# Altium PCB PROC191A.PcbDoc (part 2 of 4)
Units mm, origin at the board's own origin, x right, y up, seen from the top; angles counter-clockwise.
Board outline 150 x 100 mm, 6 copper layers (L1, L2, L3, L4, L5, L6), stack 1.608 mm thick; 309 components, 191 nets, 851 pads, 778 vias.
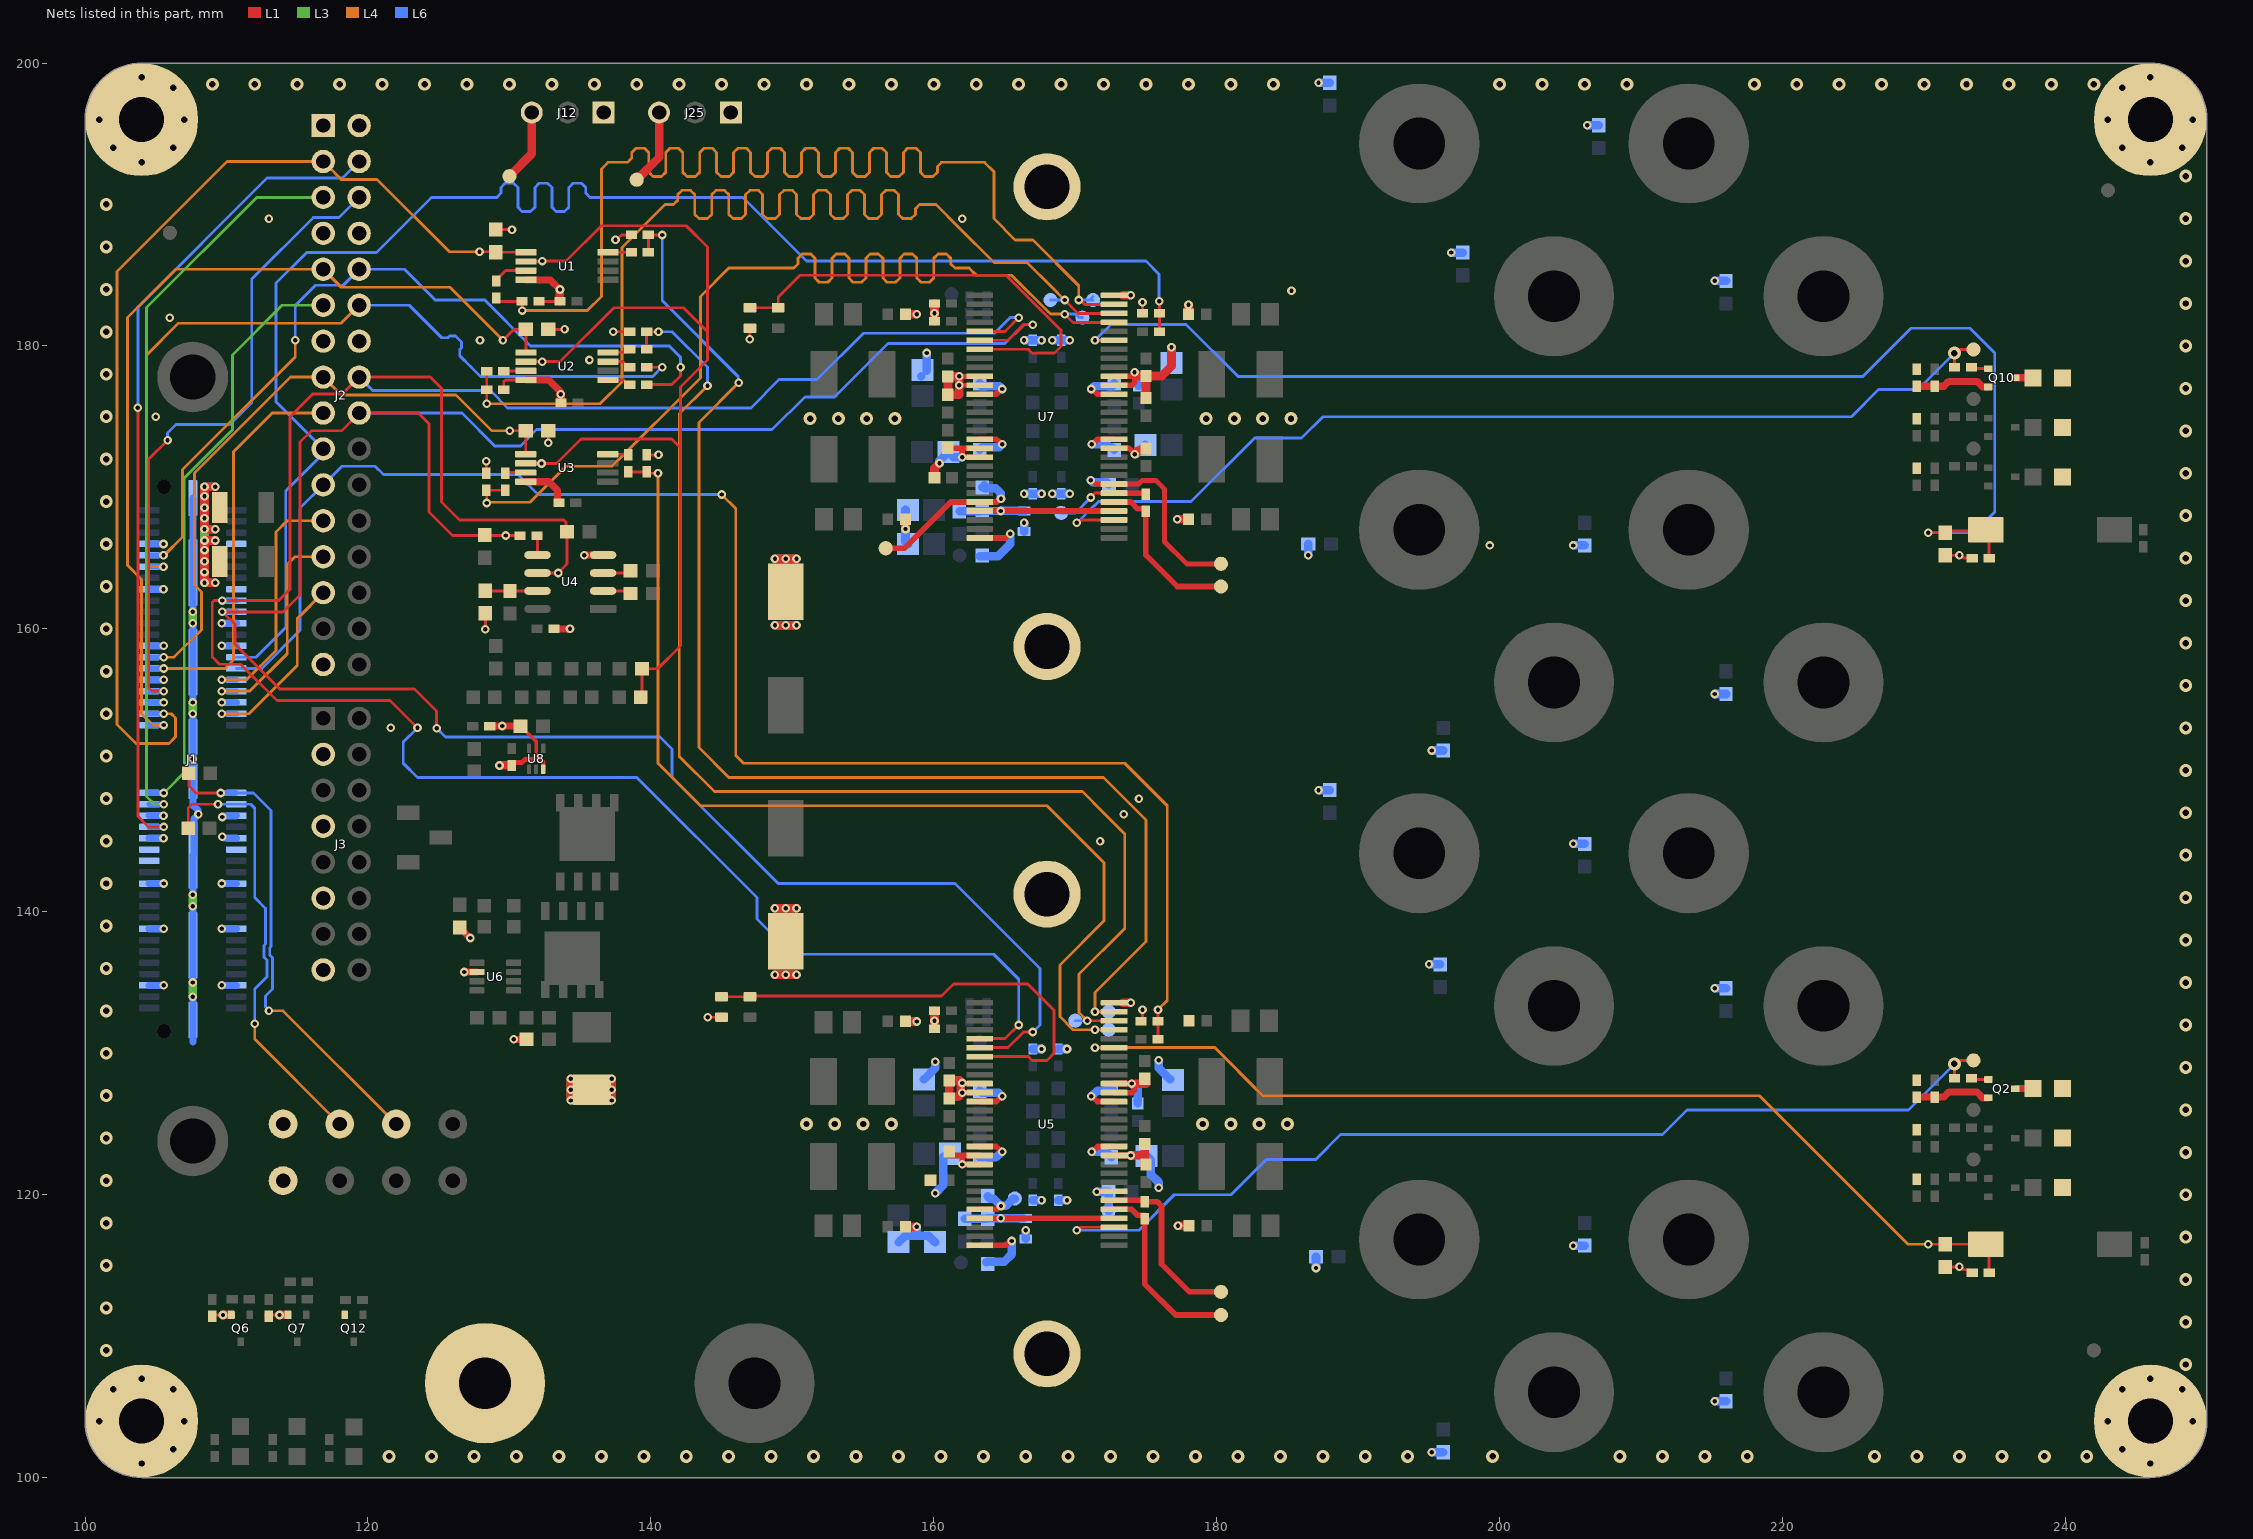
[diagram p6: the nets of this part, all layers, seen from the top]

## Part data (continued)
D5 D6 D11: library part CMP-0002888-2, "LED, Green, SMD", Color=Green, Manufacturer=Lite-On, Value1=W, Value2=2V
FID1 FID2 FID3 FID4 FID5 FID6: library part CMP-0077181-1, "Fiducial mark.  There is nothing to buy or mount.", Manufacturer=N/A
H1 H2: library part CMP-0123147-2, "20.0 x 41.4 x 32.8 mm  BGA Heat Sink - High Performance Device Specific - TI", Digikey Part Number=684-ATS-TI1OP-1918-C1-R0-ND, Manufacturer="Advanced Thermal Solutions", Operating Temperature Range=to, Thermal Resistance Forced Air Flow=4.6°C/W
J1: library part CMP-0091968-1, "80 Position Connector Header, Outer Shroud Contacts Surface Mount Gold", Digikey Part Number=SAM8132-ND, Manufacturer=Samtec, Mouser Part Number=200-QTE04001LDA, Operating Temperature Range="-55°C to +125°C", Voltage_V=225V
J2: library part CMP-0075429-1, "Header, 100mil, 16x2, Gold, TH", Color=Black, Current_A=6.3A, Manufacturer=Samtec, Supplier Part Number 1=SAM1028-16-ND, Voltage_V=550V
J3: library part CMP-0075418-1, "Header, 100mil, 8x2, Gold, TH", Color=Black, Current_A=6.3A, Manufacturer=Samtec, Supplier Part Number 1=SAM1028-08-ND, Voltage_V=550V
J4 J6 J8 J10 J13 J17 J19 J21 J23: library part CMP-0055127-1, "Binding Post, RED, TH", Manufacturer=Keystone, Supplier Part Number 1=36-7006-ND
J5 J7 J9 J11 J15 J18 J20 J22 J24: library part CMP-0055128-1, "Binding Post, BLACK, TH", Manufacturer=Keystone, Supplier Part Number 1=36-7007-ND
J12 J25: library part CMP-0055322-1, "Header, 2.54 mm, 3x1, Tin, TH", Color=White, Manufacturer=Molex, Supplier Part Number 1=WM4201-ND
L1 L2 L3 L4 L6 L7 L8 L9: library part CMP-0059924-1, "Inductor, 3.3 uH, 4.5 A, 0.038 ohm, AEC-Q200 Grade 0, SMD", Manufacturer=Cyntec, Value1="0.038 ohm", Value2=4.5A, ValueDisplayed=3.3uH
Logo1: library part CMP-0074844-2, Manufacturer="Texas Instruments"
Logo2: library part CMP-0074838-1, "Texas Instrument Corporate Signature"
Logo3: library part CMP-0074847-1, "FCC_disclaimer"
Logo4: library part CMP-0074769-4, Manufacturer="Texas Instruments"
Q1 Q2 Q3 Q9 Q10 Q11: library part CMP-0000010-3, "MOSFET, P-CH, -20 V, -0.39 A, SOT-323", Alternate Manufacturer=None, Manufacturer="Infineon Technologies", Value1=1
Q4 Q5: library part CMP-0000665-1, "MOSFET, N-CH, 30 V, 15 A, PowerPAK SO-8", Alternate Manufacturer=None, Manufacturer=Vishay-Siliconix, Supplier Part Number 1=SI7892BDP-T1-E3CT-ND, Value1=0.005, Value2="27 nC"
Q6 Q7 Q12: library part CMP-0000948-2, "MOSFET, N-CH, 100 V, 0.17 A, SOT-323", Alternate Manufacturer=None, Manufacturer="Diodes Inc.", Supplier Part Number 1=BSS123W-FDICT-ND, Value1=1
R1 R3 R9 R10 R11 R12 R14 R15 R19 R33 R78: library part CMP-0026997-2, "RES, 22, 5%, 0.1 W, AEC-Q200 Grade 0, 0402", Manufacturer=Panasonic, Power_W=100mW, Supplier Part Number 1=P22JCT-ND, TempCo="200 ppm/C", Tolerance_%=5%, Value2=0.1W, Value_Code=22R0, ValueDisplayed=22
R2 R17 R18 R20 R52 R54 R94: library part CMP-0022746-5, "RES, 10.0 k, 1%, 0.1 W, 0603", Manufacturer=Yageo, Power_W=100mW, Supplier Part Number 1=311-10.0KHRCT-ND, TempCo="100 ppm/C", Tolerance_%=1%, Value2=0.1W, Value_Code=10k0, ValueDisplayed=10.0k
R4 R41 R49 R53 R55 R74 R83 R86 R95: library part CMP-0089143-1, "0 Ohms Jumper 0.1W, 1/10W Chip Resistor 0603 (1608 Metric) Automotive AEC-Q200 Thick Film", Digikey Part Number=P0.0GCT-ND, Manufacturer=Panasonic, Mouser Part Number=667-ERJ-3GEY0R00V, Operating Temperature Range="-55°C to +155°C", Power_W=100mW, TempCo=-100/+600ppm/°C, Tolerance_%=5%
R5 R56 R57: library part CMP-0078194-1, "RES, 360, 5%, 0.1 W, AEC-Q200 Grade 0, 0402", Manufacturer=Panasonic, Power_W=100mW, Supplier Part Number 1=P360JCT-ND, TempCo="200 ppm/C", Tolerance_%=5%, Value2=0.1W, Value_Code=360R, ValueDisplayed=360
R6 R13 R16 R21 R38 R50: library part CMP-0022735-5, "RES, 100 k, 1%, 0.1 W, 0603", Manufacturer=Yageo, Power_W=100mW, Supplier Part Number 1=311-100KHRCT-ND, TempCo="100 ppm/C", Tolerance_%=1%, Value2=0.1W, Value_Code=100k
R7 R8: library part CMP-0023155-5, "RES, 4.99 k, 1%, 0.1 W, 0603", Manufacturer=Yageo, Power_W=100mW, Supplier Part Number 1=311-4.99KHRCT-ND, TempCo="100 ppm/C", Tolerance_%=1%, Value2=0.1W, Value_Code=4k99, ValueDisplayed=4.99k
R22 R23 R24 R25 R67 R68 R69 R70: library part CMP-0026753-1, "RES, 100 k, 1%, 0.063 W, AEC-Q200 Grade 0, 0402", Manufacturer="Stackpole Electronics Inc", Power_W=63mW, Supplier Part Number 1=RMCF0402FT100KCT-ND, TempCo="100 ppm/C", Tolerance_%=1%, Value2=0.063W, Value_Code=100k
R26 R31 R34 R36 R71 R76 R79 R81: library part CMP-0025805-4, "RES, 3.3, 5%, 0.1 W, AEC-Q200 Grade 0, 0603", Manufacturer=Vishay-Dale, Power_W=100mW, Supplier Part Number 1=541-3.3GCT-ND, TempCo="200 ppm/C", Tolerance_%=5%, Value2=0.1W, Value_Code=3R30, ValueDisplayed=3.3
R27 R43 R44 R48 R61 R62 R88 R89 R93: library part CMP-0078212-1, "RES, 510, 5%, 0.1 W, AEC-Q200 Grade 0, 0402", Manufacturer=Panasonic, Power_W=100mW, Supplier Part Number 1=P510JCT-ND, TempCo="200 ppm/C", Tolerance_%=5%, Value2=0.1W, Value_Code=510R, ValueDisplayed=510
R28 R29 R30 R73 R75: library part CMP-0089144-1, "1 kOhms ±5% 0.1W, 1/10W Chip Resistor 0603 (1608 Metric) Automotive AEC-Q200 Thick Film", Digikey Part Number=P1.0KGCT-ND, Manufacturer=Panasonic, Mouser Part Number=667-ERJ-3GEYJ102V, Operating Temperature Range="-55°C to +155°C", Power_W=100mW, TempCo=200ppm/°C, Tolerance_%=5%, Voltage=75V
R32 R35: library part CMP-0022752-4, "RES, 110 k, 1%, 0.1 W, 0603", Manufacturer=Yageo, Power_W=100mW, Supplier Part Number 1=311-110KHRCT-ND, TempCo="100 ppm/C", Tolerance_%=1%, Value2=0.1W, Value_Code=110k
R37 R39 R40 R42 R45 R46 R58 R60 R63 R66 R72 R77: library part CMP-0026680-1, "RES, 220, 1%, 0.1 W, AEC-Q200 Grade 0, 0402", Manufacturer=Panasonic, Power_W=100mW, Supplier Part Number 1=P220LCT-ND, TempCo="100 ppm/C", Tolerance_%=1%, Value2=0.1W, Value_Code=220R, ValueDisplayed=220
R47 R90: library part CMP-0026754-1, "RES, 10.0 k, 1%, 0.063 W, AEC-Q200 Grade 0, 0402", Manufacturer="Stackpole Electronics Inc", Power_W=63mW, Supplier Part Number 1=RMCF0402FT10K0CT-ND, TempCo="100 ppm/C", Tolerance_%=1%, Value2=0.063W, Value_Code=10k0, ValueDisplayed=10.0k
R51: library part CMP-0023253-5, "RES, 6.80 k, 1%, 0.1 W, 0603", Manufacturer=Yageo, Power_W=100mW, Supplier Part Number 1=311-6.80KHRCT-ND, TempCo="100 ppm/C", Tolerance_%=1%, Value2=0.1W, Value_Code=6k80, ValueDisplayed=6.80k
R59 R64 R65: library part CMP-0026658-1, "RES, 10.0 k, 1%, 0.1 W, 0402", Manufacturer=Panasonic, Power_W=100mW, Supplier Part Number 1=P10.0KLCT-ND, TempCo="100 ppm/C", Tolerance_%=1%, Value2=0.1W, Value_Code=10k0, ValueDisplayed=10.0k
R96: library part CMP-0023048-4, "RES, 357 k, 1%, 0.1 W, 0603", Manufacturer=Yageo, Power_W=100mW, Supplier Part Number 1=311-357KHRCT-ND, TempCo="100 ppm/C", Tolerance_%=1%, Value2=0.1W, Value_Code=357k
S1: library part CMP-0002139-2, "Switch, Slide, SPDT  100mA, SMT", CurrentRating_mA=100A, Manufacturer="Copal Electronics", Supplier Part Number 1=CAS120JCT-ND
SW2 SW4: library part CMP-0120665-1, "DIP Switch, 1 POS, SPST, Raised, 6VDC, 100mA, CFS Series", Coil Resistance_ohm=50mΩ, Contact Current Rating=100mA, Digikey Part Number=563-CFS-0103CT-ND, Manufacturer="Nidec Components Corporation", Mouser Part Number=229-CFS-0103TB, Operating Temperature Range="-40°C to +85°C"
TP1 TP2 TP3 TP7 TP8 TP9 TP10 TP11 TP12 TP13 TP14 TP15 TP16 TP17 TP18 TP19 TP23 TP24 TP25 TP26 TP27 TP28 TP29 TP30 TP31 TP32: library part CMP-0003825-1, "1mm Test Point, SMT", Manufacturer=Any, PartNumber=TP_SM_1MM
TP4 TP6 TP33: library part CMP-0055137-2, "Test Point, Miniature, Red, TH", Color=Red, Manufacturer="Keystone Electronics", Supplier Part Number 1=36-5000-ND
TP5 TP20 TP22: library part CMP-0055140-2, "Test Point, Miniature, Orange, TH", Color=Orange, Manufacturer="Keystone Electronics", Supplier Part Number 1=36-5003-ND
TP34 TP35: library part CMP-0055138-2, "Test Point, Miniature, Black, TH", Color=Black, Manufacturer="Keystone Electronics", Supplier Part Number 1=36-5001-ND
U1 U3: library part CMP-0091149-1, "Clock Clock Buffer IC 1:4 250MHz 8-TSSOP (0.173\", 4.40mm Width)", Digikey Part Number=296-LMK1C1102PWRCT-ND, Manufacturer="Texas Instruments", Max Supply Voltage=3.465V, Min Supply Voltage=1.71V, Mouser Part Number=595-LMK1C1102PWR, Nominal Supply Current=25-33000uA, Operating Temperature Range="-40°C to +125°C"
U2: library part CMP-0096980-1, "1.8-V, 2.5-V, and 3.3-V LVCMOS Clock Buffer Family", Digikey Part Number=296-LMK1C1104PWRCT-ND, Manufacturer="Texas Instruments", Max Supply Voltage=3.465V, Min Supply Voltage=1.71V, Mouser Part Number=595-LMK1C1104PWR, Nominal Supply Current=25-33000uA, Operating Temperature Range="-40°C to +125°C"
U4: library part CMP-0097697-1, "EEPROM Memory IC 4Kbit I²C 400 kHz 900 ns 8-SOIC", Digikey Part Number=CAT24C04WI-GT3OSCT-ND, Frequency_Fixed=400kHz, Manufacturer="ON Semi", Max Supply Voltage=5.5V, Min Supply Voltage=1.7V, Mouser Part Number=698-CAT24C04WI-GT3, Nominal Supply Current=1-2mA, Operating Temperature Range="-40°C to +85°C"
U5 U7: library part CMP-0096441-1, "26.4 V, 7.5 A Digital Input 4-Channel Automotive Class-D Audio Amplifier with Current Sense and Real-time Load Diagnostics", Manufacturer="Texas Instruments", Max Supply Voltage=26.4V, Min Supply Voltage=4.5V, Operating Temperature Range="-40°C to +125°C", Part Number=TAS6554QDKQRQ1, Power At Speaker R="50W @ 2Ω"
U6: library part CMP-0095578-1, "Low IQ High Side Switch Controller With Reverse Polarity and Overvoltage Protection", Manufacturer="Texas Instruments", Max Supply Voltage=60V, Min Supply Voltage=4V, Nominal Supply Current=45uA, Operating Temperature Range="-40°C to +150°C", Part Number=LM74502QDDFRQ1
U8: library part CMP-0051698-3, "Low-Power Single Schmitt-Trigger Buffer, DRL0005A", Alternate Manufacturer="Texas Instruments", F @ Nom Voltage(Max)(Mhz)=100, Generic Part Number=SN74AUP1G17, ICC @ Nom Voltage(Max)(mA)=0.0009, Operating Temperature Range(C)="-40 to 85", Rating=Catalog, tpd @ Nom Voltage(Max)(ns)=35.1,18.1,12.9,11,7.9,6.7, Voltage(Nom)(V)=0.8,1.2,1.5,1.8,2.5,3.3
ZZ2: library part CMP-0077236-1
ZZ3: library part CMP-0077237-1
ZZ4: library part CMP-0077238-1

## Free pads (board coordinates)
  round 8 hole 3.2: ""(104,104) ""(104,196) ""(246,104) ""(246,196)
  round 5 hole 3.2: ""(107.62,123.8) ""(107.62,177.8)

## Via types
v1: diameter 0.61, hole 0.305, L1 to L6, tented both sides, 566 vias
v2: diameter 0.914, hole 0.457, L1 to L6, tented both sides, 188 vias
v3: diameter 0.5, hole 0.2, L1 to L6, 24 vias

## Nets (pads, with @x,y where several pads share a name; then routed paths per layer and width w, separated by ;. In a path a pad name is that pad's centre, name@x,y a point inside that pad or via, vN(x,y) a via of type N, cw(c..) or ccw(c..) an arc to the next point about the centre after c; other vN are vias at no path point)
AECCLKIN: J1.33 J2.6 | length 46.3
  L1 w0.2: v1(105.575,155.6) 104.727,155.6 104.5,155.827 104.5,171.989 v1(105.836,173.325)
  L6 w0.2: v1(105.836,173.325) 105.836,173.836 106.44,174.44 110.236,174.44 111.79,175.994 111.79,184.736 116.139,189.085 117.965,189.085 J2.6@119.38,190.5
  L6 w0.4: J1.33@104.535,155.6 v1(105.575,155.6)
AECCLKOUT: J1.47 J2.4 | length 59.1
  L1 w0.2: v1(103.738,175.625) 103.75,175.613 103.75,146.75 104.5,146 v1(105.575,146)
  L6 w0.2: v1(103.738,175.625) 103.738,182.738 112.864,191.864 118.204,191.864 J2.4@119.38,193.04
  L6 w0.4: J1.47@104.535,146 v1(105.575,146)
AREF0: C74.1 U7.56 | length 5.5
  L1 w0.4: U7.56@163.25,166.428 165.07,166.428 165.375,166.733 v1(165.409,166.733)
  L6 w0.6: C74.1@163.25,165.133 164.541,165.133 165.409,166 v1(165.409,166.733)
AREF1: C16.1 U5.56 | length 5.3
  L1 w0.4: U5.56@163.25,116.428 165.07,116.428 165.375,116.733 v1@165.409,116.733
  L6 w0.6: C16.1@163.717,115.218 163.776,115.277 164.989,115.277 165.509,115.797 v1(165.509,116.733)
AVSS0: C76.2 C77.1 R75.2 U7.4 U7.53 | length 14
  L1 w0.4: U7.53@163.25,168.333 v1@164.611,168.333 ; v1(164.742,168.333) U7.4@172.75,168.333
  L6 w0.4: C76.2@161.801,168.3 C76.2@161.817,168.316 ; C77.1@163.234,168.316 C77.1@163.25,168.333
  L6 w0.6: C76.2@161.817,168.316 C77.1@163.234,168.316 ; C77.1@163.25,168.333 v1(164.742,168.333) ; v1@164.747,168.338 166.377,168.338 R75.2@166.382,168.332
AVSS1: C18.2 C19.1 R30.2 U5.4 U5.53 | length 13.5
  L1 w0.4: U5.53@163.25,118.333 v1@164.611,118.333 ; v1(164.742,118.333) U5.4@172.75,118.333
  L6 w0.4: v1(164.742,118.333) v1@164.745,118.33 ; R30.2@166.487,118.328 R30.2@166.49,118.325
  L6 w0.6: C18.2@162.2,118.3 162.216,118.316 163.686,118.316 C19.1@163.702,118.3 ; C19.1@163.734,118.333 v1(164.742,118.333) ; v1@164.745,118.33 R30.2@166.315,118.33
BST_1P0: C80.1 U7.40 | length 3.5
  L1 w0.4: U7.40@163.25,176.588 164.415,176.588 164.784,176.956 v1(164.841,176.956)
  L6 w0.6: C80.1@163.25,177.35 163.25,177.325 163.425,177.15 164.644,177.15 164.838,176.956 v1(164.841,176.956)
BST_1P1: C22.1 U5.40 | length 3.5
  L1 w0.4: U5.40@163.25,126.588 164.415,126.588 164.784,126.956 v1(164.841,126.956)
  L6 w0.6: C22.1@163.25,127.35 163.4,127.2 164.594,127.2 164.838,126.956 v1(164.841,126.956)
BST_2P0: C75.1 U7.45 | length 3.5
  L1 w0.4: U7.45@163.218,173.413 U7.45@163.25,173.413 164.415,173.413 v1(164.841,173.044)
  L6 w0.6: C75.1@163.25,172.65 163.25,172.672 163.425,172.847 164.615,172.847 164.81,173.042 164.839,173.042 v1(164.841,173.044)
BST_2P1: C17.1 U5.45 | length 3.5
  L1 w0.4: U5.45@163.218,123.413 U5.45@163.25,123.413 164.415,123.413 v1(164.841,123.044)
  L6 w0.6: C17.1@163.25,122.65 164.39,122.65 v1(164.841,123.044)
BST_3P: C14.1 U5.17 | length 3.5
  L1 w0.4: v1(171.127,126.956) 171.552,126.588 U5.17@172.75,126.588
  L6 w0.6: v1(171.127,126.956) 171.578,127.35 C14.1@172.718,127.35
BST_3P0: C72.1 U7.17 | length 3.6
  L1 w0.4: v1(171.127,176.956) 171.552,176.588 U7.17@172.75,176.588
  L6 w0.6: v1(171.127,176.956) 171.129,176.958 171.136,176.958 171.329,177.15 172.575,177.15 172.75,177.325 C72.1@172.75,177.35
BST_4P0: C65.1 U7.12 | length 3.5
  L1 w0.4: v1(171.159,173.044) 171.216,173.044 171.585,173.413 U7.12@172.75,173.413
  L6 w0.6: v1(171.159,173.044) 172.224,173.044 172.418,172.85 172.575,172.85 172.75,172.675 C65.1@172.75,172.65
BST_4P1: C7.1 U5.12 | length 3.3
  L1 w0.4: v1(171.159,123.044) 171.216,123.044 171.585,123.413 U5.12@172.75,123.413
  L6 w0.6: v1(171.159,123.044) 172.026,123.044 172.22,122.85 172.378,122.85 172.553,122.675 C7.1@172.553,122.65
CP0: C105.1 TP27.1 U7.7 | length 15.5
  L1 w0.35: v1(171.089,170.506) 171.159,170.506 171.428,170.238 174.469,170.238 174.731,170.5 175.7,170.5 176.3,169.9 176.3,166.18 177.88,164.6 TP27.1@180.3,164.6
  L6 w0.35: C105.1@172.37,170.2 C105.1@172.39,170.18
  L6 w0.6: v1(171.089,170.506) 171.092,170.506 171.243,170.355 172.215,170.355 C105.1@172.35,170.22
CP1: C47.1 TP11.1 U5.7 | length 3.4
  L1 w0.35: v1@171.504,120.234 U5.7@172.746,120.234
  L6 w0.6: v1(171.529,120.209) C47.1@172.361,120.209 TP11.1@172.361,118.837
CPC_BOT0: C92.1 TP26.1 U7.5 | length 11.9
  L1 w0.4: U7.5@172.75,168.968 173.929,168.968 174.407,168.489 174.89,168.489 174.99,168.389 C92.1@174.99,168.323 174.99,165.227 177.216,163 TP26.1@180.3,163
CPC_BOT1: C34.1 TP10.1 U5.5 | length 13.5
  L1 w0.4: U5.5@172.746,118.964 173.989,118.964 174.404,118.548 174.865,118.548 174.99,118.423 174.99,118.323 174.9,118.234 174.9,113.7 177.1,111.5 TP10.1@180.3,111.5
CPC_TOP0: C92.2 TP25.1 U7.6 | length 6.6
  L1 w0.2: v1@171.089,169.3 171.405,169.616 172.662,169.616 172.7,169.653 U7.6@172.75,169.603
  L1 w0.35: C92.2@174.914,169.599 C92.2@174.99,169.523
  L1 w0.4: U7.6@172.746,169.599 C92.2@174.914,169.599
  L6 w0.2: TP25.1@169,168.2 170.004,168.2 v1(171.089,169.285)
CPC_TOP1: C34.2 TP9.1 U5.6 | length 12.7
  L1 w0.4: U5.6@172.746,119.599 174.914,119.599 C34.2@174.99,119.523 ; C34.2@174.9,119.5 175.803,119.5 176.098,119.205 176.098,115.102 178.068,113.132 TP9.1@180.3,113.132
ECAP_FRAMESYNC1: J1.9 J2.10 R11.2 | length 57.4
  L1 w0.2: R11.2@139.7,177.25 139.725,177.275 141.475,177.275 142.088,177.888 142.088,178.48 v1(142.1,178.493)
  L4 w0.2: v1(105.55,165.2) 105.605,165.2 106.9,166.495 106.9,171.264 114.864,179.229 v1(114.864,180.407)
  L6 w0.2: v1(114.864,180.407) 114.864,182.864 116.295,184.295 118.255,184.295 J2.10@119.38,185.42 122.58,185.42 124.755,183.245 128.255,183.245 131.5,180 141.3,180 142.1,179.2 v1(142.1,178.493)
  L6 w0.4: J1.9@104.535,165.2 v1(105.55,165.2)
ECAP_FRAMESYNC2: J1.11 J2.12 R12.2 | length 59.2
  L1 w0.2: R12.2@139.7,178.5 v1(140.8,178.5)
  L4 w0.2: v1(105.55,164.4) 104.6,164.4 104.343,164.657 104.343,179.343 106.61,181.61 118.11,181.61 J2.12@119.38,182.88
  L6 w0.2: J2.12@119.38,182.88 122.92,182.88 125.151,180.649 125.221,180.579 125.646,180.579 125.768,180.701 126.192,180.701 126.616,180.276 126.616,179.852 126.494,179.73 126.494,179.306 127.277,178.523 127.347,178.453 127.949,177.851 140.129,177.851 140.778,178.5 v1(140.8,178.5)
  L6 w0.4: J1.11@104.535,164.4 v1(105.55,164.4)
EEPROM_A1: R18.2 U4.2 | length 2
  L1 w0.2: U4.2@136.618,162.679 138.371,162.679 R18.2@138.55,162.5
EEPROM_A2: R20.2 U4.3 | length 2
  L1 w0.2: U4.3@136.618,163.949 138.399,163.949 R20.2@138.55,164.1
EEPROM_WP: R17.2 R21.2 U4.7 | length 3.7
  L1 w0.2: R21.2@128.3,162.7 128.321,162.679 R17.2@130.041,162.679 U4.7@131.986,162.679
FAN0_SENSE: J25.3 TP31.1 | length 5.4
  L1 w0.61: TP31.1@139,191.75 140.58,193.33 J25.3@140.58,196.5
FAN1_SENSE: J12.3 TP15.1 | length 5.2
  L1 w0.61: TP15.1@130,192 131.58,193.58 J12.3@131.58,196.5
FAULT_LEDPWR0: Q10.2 R66.2 R77.1 | length 5.3
  L1 w0.5: R77.1@229.5,177.15 R66.2@230.75,177.15 231.405,177.15 ; 231.455,177.205 231.75,177.5 233.75,177.5 234.15,177.1 Q10.2@234.55,177.1
FAULT_LEDPWR1: Q2.2 R42.2 R46.1 | length 5.3
  L1 w0.5: R46.1@229.5,126.9 R42.2@230.75,126.9 231.405,126.9 ; 231.455,126.955 231.75,127.25 233.75,127.25 234.15,126.85 Q2.2@234.55,126.85
FAULT_N0: R89.2 TP30.1 U7.3 | length 72
  L1 w0.2: v1(170.111,167.494) 170.222,167.494 170.425,167.698 U7.3@172.75,167.698 ; R89.2@232.15,178.5 v2(232.15,179.5) ; v2@232.343,179.5 232.593,179.75 TP30.1@233.5,179.75
  L6 w0.2: v1(170.111,167.494) 171.297,168.68 171.34,168.68 171.66,169 178.183,169 182.683,173.5 186,173.5 187.5,175 224.872,175 226.784,176.912 229.562,176.912 v2(232.15,179.5)
FAULT_N1: R44.2 TP14.1 U5.3 | length 71.9
  L1 w0.2: v1(170.111,117.494) 170.222,117.494 170.425,117.698 U5.3@172.75,117.698 ; R44.2@232.15,128.25 v2(232.15,129.25) ; v2@232.343,129.25 232.593,129.5 TP14.1@233.5,129.5
  L6 w0.2: v1(170.111,117.494) 174.494,117.494 177,120 181,120 183.5,122.5 187,122.5 188.75,124.25 211.5,124.25 213.25,126 228.9,126 v2(232.15,129.25)
FAULT_N_L0: D9.1 Q10.3 | length 1.3
  L1 w0.5: Q10.3@236.45,177.75 D9.1@237.7,177.75
FAULT_N_L1: D2.1 Q2.3 | length 1.3
  L1 w0.5: Q2.3@236.45,127.5 D2.1@237.7,127.5
FAULT_N_R0: Q10.1 R89.1 | length 1.2
  L1 w0.2: R89.1@233.35,178.5 233.45,178.4 Q10.1@234.55,178.4
FAULT_N_R1: Q2.1 R44.1 | length 1.1
  L1 w0.2: R44.1@233.45,128.15 Q2.1@234.55,128.15
GND: C1.1 C2.1 C3.1 C4.1 C5.1 C6.1 C9.2 C10.2 C11.2 C12.2 C13.2 C15.1 C21.2 C23.2 C24.2 C25.1 C26.2 C27.2 C28.2 C29.2 C30.2 C32.2 C35.2 C36.2 C37.2 C38.1 C39.1 C40.1 C41.1 C42.1 C43.1 C44.1 C45.1 C46.1 C48.2 C49.2 C53.2 C54.2 C55.2 C56.1 C57.1 C58.2 C59.2 C64.2 C67.2 C68.2 C69.2 C70.2 C71.2 C73.1 C79.2 C81.2 C82.2 C83.1 C84.2 C85.2 C87.2 C88.2 C93.2 C94.2 C95.2 C96.1 C97.1 C98.1 C99.1 C100.1 C101.1 C102.1 C103.1 C104.1 C106.2 C107.2 C111.2 C112.2 C113.2 C114.1 C116.2 D1.2 D2.2 D3.2 D4.1 D8.2 D9.2 D10.2 H1.1 H1.2 H2.1 H2.2 J1.7 J1.8 J1.15 J1.16 J1.22 J1.25 J1.26 J1.31 J1.35 J1.36 J1.45 J1.46 J1.49 J1.50 J1.57 J1.58 J1.65 J1.66 J1.75 J1.76 J1.P1 J1.P2 J2.1 J2.2 J2.7 J2.8 J2.13 J2.14 J2.31 J3.3 J3.7 J3.11 J3.15 J12.1 J15.1 J25.1 pad.@104,104 pad.@104,196 pad.@246,104 pad.@246,196 Q6.2 Q7.2 Q12.2 R6.1 R13.1 R16.1 R21.1 R22.1 R23.1 R24.1 R25.1 R29.1 R30.1 R32.1 R35.1 R38.1 R39.2 R45.2 R46.2 R51.1 R60.2 R64.2 R65.2 R67.1 R68.1 R69.1 R70.1 R72.2 R74.1 R75.1 R77.2 TP34.1 TP35.1 U1.4 U2.4 U3.4 U4.4 U5.11 U5.18 U5.19 U5.28 U5.38 U5.39 U5.46 U5.47 U6.2 U7.11 U7.18 U7.19 U7.28 U7.38 U7.39 U7.46 U7.47 U8.3 | length 251.5
  L1 w0.2: R64.2@109,111.5 v1(109.75,111.5) ; R65.2@113,111.5 v1(113.75,111.5) ; J15.1@127,106.5 J15.1@127,106.68 ; v1(128.3,159.965) R21.1@128.3,161.1 ; R69.1@128.365,171 v1(128.365,171.84) ; R6.1@129.033,188.222 v1(130.183,188.222) ; R68.1@129.6,176.989 129.6,177.473 129.717,177.59 U2.4@131.167,177.59 ; 131.886,150.775 131.911,150.8 132.163,150.8 ; R67.1@132.086,183.148 C3.1@133.573,183.148 ; v1(132.75,173.16) R16.1@132.75,174 ; R13.1@132.75,181.17 v1(133.9,181.17) ; v1(135.283,165.198) v1@135.294,165.208 ; U4.4@136.608,165.208 U4.4@136.618,165.219 ; v1(137.35,181) R23.1@138.5,181 ; v1(137.5,187.5) 137.579,187.5 137.925,187.845 R22.1@138.625,187.845 ; R24.1@139.7,172.3 v1(140.54,172.3) ; v1@144.022,132.548 v1(144.024,132.55) R29.1@145,132.55 ; v1(146.994,180.466) R74.1@147,181.25 ; R25.1@174.75,132.303 v1(174.756,133.086) ; R70.1@174.75,182.303 v1(174.756,183.086) ; R32.1@231.5,114.9 v1(232.5,114.9) 232.611,114.9 232.811,114.7 233.2,114.7 C58.2@233.4,114.5 ; R35.1@231.5,165.2 v1(232.5,165.2) 232.606,165.2 232.806,165 C116.2@233.4,165
  L1 w0.25: R38.1@130.786,153.127 130.811,153.127 131.911,152.027 131.911,150.8
  L1 w0.3: U8.3@132.386,150.065 132.386,150.551
  L1 w0.35: C57.1@130.15,150.345 130.15,150.445 130.275,150.57 130.905,150.57 131.11,150.775 131.886,150.775 132.163,150.775 132.386,150.551 ; v1@161.55,177.849 v1@161.735,177.85 ; v1@161.735,177.85 v1(161.801,177.85) U7.38@163.246,177.854 ; v1(161.805,177.218) U7.39@163.25,177.223 ; v1(162,127.2) 162.011,127.211 163.239,127.211 U5.39@163.25,127.223 ; v1(162,127.9) 162.021,127.879 163.229,127.879 U5.38@163.25,127.858 ; U7.38@163.25,177.858 U7.38@163.258,177.849 ; U5.28@172.75,133.573 v1@173.996,133.576 ; U7.28@172.75,183.573 v1@173.996,183.576
  L1 w0.4: C38.1@161,122.787 161.01,122.778 162.007,122.778 ; C98.1@161,172.787 161.01,172.778 162.007,172.778 ; U5.47@163.25,122.143 v1(162.007,122.143) 162.007,122.778 ; U5.46@163.25,122.778 162.007,122.778 ; U7.47@163.25,172.143 v1(162.007,172.143) 162.007,172.778 ; U7.46@163.25,172.778 162.007,172.778 ; U5.18@172.746,127.219 174.011,127.219 174.216,127.424 174.216,127.851 v1@174.21,127.858 ; U7.11@172.746,172.778 U7.11@172.75,172.778 173.801,172.778 174.214,172.365 v1(174.214,172.353) ; U7.18@172.746,177.219 174.011,177.219 174.216,177.424 174.216,177.851 v1@174.21,177.858 ; U5.11@172.75,122.778 v1(173.923,122.778) ; U5.19@172.75,127.854 172.754,127.858 v1(173.989,127.858) ; U7.19@172.75,177.854 172.754,177.858 173.989,177.858 ; C45.1@174.813,122.338 C45.1@175,122.151 ; 174.838,122.778 174.9,122.839
  L1 w0.5: C64.2@126.5,138.9 126.5,138.875 v1(127.225,138.15) ; v1(126.8,135.743) U6.2@127.7,135.743 ; C28.2@128.6,153.134 v1(129.5,153.134) R38.1@130.799,153.127 ; v1(130.304,130.988) R51.1@131.204,130.988 ; U3.4@131.15,170.4 132.805,170.4 133.405,169.8 133.405,168.95 133.455,168.9 C5.1@133.5,168.9 ; U2.4@131.167,177.59 132.784,177.59 133.137,177.237 133.613,176.761 133.613,176.616 v1(133.634,176.595) ; U1.4@131.173,184.673 132.887,184.673 v1(133.572,183.988) ; C6.1@133.15,160 v1(134.285,160) ; v1@135.294,165.208 U4.4@136.608,165.208
  L1 w0.6: v1(109.75,111.5) Q6.2@110.125,111.5 ; R65.2@113,111.4 R65.2@113,111.5 ; v1(113.75,111.5) Q7.2@114.125,111.5 ; v1(129.3,150.345) C57.1@130.15,150.345 ; C3.1@133.573,183.148 v1(133.572,183.988) ; v1(133.634,176.595) 133.636,176.593 133.636,176 C4.1@133.65,176 ; v1(134.33,126.667) v1(134.33,127.429) v1(134.33,128.191) ; v1(137.226,126.667) v1(137.226,127.429) v1(137.226,128.191) ; v1(148.768,135.56) v1(149.53,135.56) v1(150.292,135.56) ; v1(148.768,140.26) v1(149.53,140.26) v1(150.292,140.26) ; v1(148.768,160.26) v1(149.53,160.26) v1(150.292,160.26) ; v1(148.768,164.96) v1(149.53,164.96) v1(150.292,164.96) ; v1@173.925,122.776 v1(173.923,122.778) 174.838,122.778 ; C44.1@174.794,123.472 174.794,123.494 C44.1@174.9,123.6 ; C45.1@174.9,122.1 174.9,122.839 C44.1@174.9,123.578
  L1 w0.61: v1(109.2,163.25) v1(108.445,163.25) v1(108.445,166.25) v1(109.2,166.25) ; v1(109.2,167.052) v1(108.445,167.052) v1(108.445,170.052) v1(109.2,170.052) ; C35.2@158.003,117.75 v1(158.787,117.744) ; C53.2@158.003,132.25 v1(158.787,132.244) ; v1(158.003,167.063) C93.2@158.003,167.75 ; C111.2@158.003,182.25 v1(158.787,182.244) ; C103.1@160.049,170.7 160.049,171.349 v1(160.4,171.7) ; C13.2@160.05,131.75 v1(160.05,132.303) C12.2@160.05,133 ; C71.2@160.05,181.75 v1(160.05,182.303) C70.2@160.05,183 ; C41.1@161.1,128 C40.1@161.1,126.8 161.1,126.822 161.201,126.923 161.723,126.923 v1(162,127.2) 161.91,127.29 161.91,127.81 v1(162,127.9) 161.825,128.075 C41.1@161.1,128.075 ; v1@161.735,177.85 v1(161.801,177.85) ; U5.28@173.373,133.574 v1(173.923,133.574) ; U7.28@173.373,183.574 v1(173.923,183.574) ; v1@174.21,127.858 174.992,127.858 C42.1@175,127.849 ; v1@174.21,177.858 174.992,177.858 175,177.849 C102.1@175,176.318 ; v1(174.214,172.353) 174.49,172.628 174.899,172.628 C100.1@175,172.729 ; C101.1@175,177.875 176.116,177.875 176.8,178.559 v1(176.8,179.9) ; v1(177.216,167.756) C67.2@178,167.75 ; v1(177.263,117.806) C9.2@178.047,117.8 ; C79.2@177.997,182.25 178,182.253 v1(178,182.913) ; v1(161.801,177.85) 161.735,177.85 C96.1@161,177.849 C97.1@161,176.551 161.801,176.552 v1(161.801,177.85)
  L3 w0.6: v1(134.33,126.667) v1(134.33,128.191) ; v1(137.226,126.667) v1(137.226,128.191) ; v1(148.768,135.56) v1(149.53,135.56) v1(150.292,135.56) ; v1(148.768,140.26) v1(149.53,140.26) v1(150.292,140.26) ; v1(148.768,160.26) v1(149.53,160.26) v1(150.292,160.26) ; v1(148.768,164.96) v1(149.53,164.96) v1(150.292,164.96)
  L3 w0.61: v1(107.62,134) v1(107.62,135) ; v1(107.62,140.4) v1(107.62,141.2) ; v1(107.62,154) v1(107.62,154.8) ; v1(107.62,160.4) v1(107.62,161.2) ; v1(108.445,163.25) v1(108.445,170.052)
  L6 w0.2: v1(109.2,166.25) v1@109.311,166.25
  L6 w0.4: C84.2@161.025,172.5 C84.2@161.383,172.143 ; C30.2@174.734,122.778 C30.2@175.049,122.462
  L6 w0.5: J1.75@104.535,134.8 v1(105.575,134.8) ; J1.65@104.535,138.8 v1(105.575,138.8) ; J1.57@104.535,142 v1(105.575,142) ; J1.49@104.535,145.2 v1(105.55,145.2) ; J1.45@104.535,146.8 v1(105.55,146.8) ; J1.35@104.535,154.8 v1(105.575,154.8) ; J1.31@104.535,156.4 v1(105.575,156.4) ; J1.25@104.535,158.8 v1(105.575,158.8) ; J1.15@104.535,162.8 v1(105.55,162.8) ; J1.7@104.535,166 v1(105.55,166) ; 107.62,130.8 J1.P2@107.62,132.36 v1(107.62,134) v1(107.62,135) J1.P2@107.62,137.63 v1(107.62,140.4) v1(107.62,141.2) J1.P2@107.62,143.98 107.69,144.05 107.69,146.552 108.017,146.879 v1(108.017,146.9) 107.996,146.921 107.996,147.194 107.62,147.57 v1(107.62,150.8) J1.P1@107.62,152.36 v1(107.62,154) v1(107.62,154.8) J1.P1@107.62,157.63 v1(107.62,160.4) v1(107.62,161.2) J1.P1@107.62,163.98 J1.P1@107.62,169.25 ; v1(109.665,134.8) J1.76@110.705,134.8 ; v1(109.665,138.8) J1.66@110.705,138.8 ; v1(109.665,142) J1.58@110.705,142 ; v1(109.665,154.8) J1.36@110.705,154.8 ; v1(109.665,158.8) J1.26@110.705,158.8 ; v1(109.665,160.4) J1.22@110.705,160.4 ; v1(109.7,145.3) 109.73,145.3 109.81,145.22 110.685,145.22 J1.50@110.705,145.2 ; v1(109.7,146.7) 109.73,146.7 109.81,146.78 110.685,146.78 J1.46@110.705,146.8
  L6 w0.6: C49.2@157.512,116.626 157.989,117.103 158.59,117.103 ; 158.687,117.2 158.59,117.103 ; 158.787,117.3 158.984,117.103 ; C26.2@159.3,128.151 C26.2@159.3,128.151 160.098,128.948 160.098,129.398 v1(160.1,129.4) ; C48.2@160.101,116.626 159.625,117.103 158.984,117.103 ; v1(160.101,120.102) 160.101,120.105 160.675,120.679 C27.2@160.675,122.7 ; C84.2@161.383,172.143 v1(162.007,172.143) ; v1(173.923,122.778) C30.2@174.734,122.778 ; v1(173.989,127.858) 174.4,127.446 C43.1@174.4,126.451 ; v1(174.214,172.353) 174.216,172.355 174.305,172.355 C88.2@174.949,173 C88.2@174.949,173 ; C30.2@175.049,122.749 175.352,122.446 175.352,121.425 175.898,120.879 175.898,120.502 v1(175.9,120.5) ; v1@175.9,129.497 175.9,128.949 176.699,128.151 C29.2@176.7,128.151 ; 158.59,117.103 158.984,117.103
  L6 w0.61: v1(109.2,163.25) v1(108.445,163.25) v1(108.445,166.25) v1(109.2,166.25) ; v1(109.2,167.052) v1(108.445,167.052) v1(108.445,170.052) v1(109.2,170.052) ; C106.2@158.003,168.405 158.003,166.171 C107.2@158.175,166 ; 158.687,117.2 158.787,117.3 v1(158.787,117.744) ; C85.2@159.101,177.85 C85.2@159.1,177.851 ; v1(159.5,179.5) C85.2@159.509,178.251 ; v1(160.4,171.7) 160.4,171.873 C84.2@161.025,172.5 C84.2@161.025,172.5 ; R75.1@166.382,166.882 v1(166.382,167.499) ; v1(166.382,169.55) C104.1@167,169.55 v1(167.617,169.55) ; v1(166.382,180.4) C114.1@167,180.4 v1(167.617,180.4) ; R30.1@166.49,116.875 v1(166.49,117.493) ; C46.1@167,119.6 v1(167.617,119.6) ; C56.1@167,130.3 v1(167.617,130.3) ; v1(168.383,169.55) C73.1@169,169.55 v1(169.617,169.55) ; v1(168.383,180.4) C83.1@169,180.4 v1(169.617,180.4) ; C15.1@168.8,119.6 v1(169.417,119.6) ; C25.1@168.8,130.3 v1(169.417,130.3) ; v1(174.194,178.131) 174.399,177.926 174.399,177.305 C99.1@174.5,177.203 ; C87.2@176.8,178.783 v1(176.8,179.9) ; v1(186.468,165.2) C68.2@186.468,166 ; v1(187.017,114.817) C10.2@187.017,115.618 ; v1(187.2,148.6) C54.2@188,148.6 ; v1(187.2,198.6) C112.2@188,198.6 ; v1(195.01,136.286) C23.2@195.81,136.286 ; v1(195.2,101.8) C36.2@196,101.8 ; v1(195.2,151.4) C94.2@196,151.4 ; v1(196.582,186.6) C81.2@197.383,186.6 ; v1(205.2,116.4) C11.2@206,116.4 ; v1(205.2,144.8) C55.2@206,144.8 ; v1(205.2,165.9) C69.2@206,165.9 ; v1(206.2,195.6) C113.2@207,195.6 ; v1(215.2,105.4) C37.2@216,105.4 ; v1(215.2,134.6) C24.2@216,134.6 ; v1(215.2,155.4) C95.2@216,155.4 ; v1(215.2,184.6) C82.2@216,184.6
  other v1: 175.9,129.5 171.755,144.991 173.418,146.9 174.5,148 121.605,153 108.445,164.015 108.445,164.77 108.445,165.57 199.3,165.9 108.445,167.817 108.445,168.572 108.445,169.372 105,175 135.655,179.005 127.921,180.407 106,182 185.282,183.9 113,189 162,189
  other v2: 104,101 246,101 121.5,101.5 124.5,101.5 127.5,101.5 130.5,101.5 133.5,101.5 136.5,101.5 139.5,101.5 142.5,101.5 145.5,101.5 148.5,101.5 151.5,101.5 154.5,101.5 157.5,101.5 160.5,101.5 163.5,101.5 166.5,101.5 169.5,101.5 172.5,101.5 175.5,101.5 178.5,101.5 181.5,101.5 184.5,101.5 187.5,101.5 190.5,101.5 193.5,101.5 199.5,101.5 208.5,101.5 211.5,101.5 214.5,101.5 217.5,101.5 226.5,101.5 229.5,101.5 232.5,101.5 235.5,101.5 238.5,101.5 241.5,101.5 106.243,102 244,102 101,104 107,104 243,104 249,104 102,106.243 106.243,106.243 244,106.243 248.243,106.243 104,107 246,107 248.5,108 101.5,109 248.5,111 101.5,112 248.5,114 101.5,115 248.5,117 101.5,118 248.5,120 101.5,121 248.5,123 101.5,124 151,125 153,125 155,125 157,125 179,125 181,125 183,125 185,125 248.5,126 101.5,127 248.5,129 101.5,130 248.5,132 101.5,133 248.5,135 101.5,136 248.5,138 101.5,139 248.5,141 101.5,142 248.5,144 101.5,145 248.5,147 101.5,148 248.5,150 101.5,151 248.5,153 101.5,154 248.5,156 101.5,157 248.5,159 101.5,160 248.5,162 101.5,163 248.5,165 101.5,166 248.5,168 101.5,169 248.5,171 101.5,172 248.5,174 151.25,174.857 153.25,174.857 155.25,174.857 157.25,174.857 179.25,174.857 181.25,174.857 183.25,174.857 185.25,174.857 101.5,175 248.5,177 101.5,178 248.5,180 101.5,181 248.5,183 101.5,184 248.5,186 101.5,187 248.5,189 101.5,190 248.5,192 104,193 246,193 102,194 106.243,194 244,194 248.243,194 101,196 107,196 243,196 249,196 106.243,198.243 244,198.243 109,198.5 112,198.5 115,198.5 118,198.5 121,198.5 124,198.5 127,198.5 130,198.5 133,198.5 136,198.5 139,198.5 142,198.5 145,198.5 148,198.5 151,198.5 154,198.5 157,198.5 160,198.5 163,198.5 166,198.5 169,198.5 172,198.5 175,198.5 178,198.5 181,198.5 184,198.5 200,198.5 203,198.5 206,198.5 209,198.5 218,198.5 221,198.5 224,198.5 227,198.5 230,198.5 233,198.5 236,198.5 239,198.5 242,198.5 104,199 246,199
GPIO0: J1.42 R86.2 TP20.1 | length 34.3
  L1 w0.2: R86.2@107.349,149.8 107.349,148.883 107.832,148.4 v1(109.6,148.4)
  L4 w0.2: v1(113,133) 114,133 TP20.1@122,125
  L6 w0.2: J1.42@110.705,148.4 111.921,148.4 113.155,147.166 113.155,137.55 113.055,137.451 113.055,136.949 113.254,136.751 113.254,134.543 112.755,134.043 112.755,133.271 113,133.026 v1(113,133)
  L6 w0.4: v1(109.6,148.4) J1.42@110.64,148.4
GPIO0_MCASP_BUFFER_EN: R2.2 R4.1 U1.2 U2.2 U3.2 | length 75.9
  L1 w0.2: U3.2@131.117,171.69 v1(132.267,171.69) 133.34,171.69 135.063,173.413 141.475,173.413 142.1,172.788 ; U2.2@131.167,178.89 v1(132.317,178.89) 133.581,178.89 137.391,182.7 142.3,182.7 144,181 ; U1.2@131.173,185.973 v1@132.322,185.973 ; v1(132.322,186) 134,186 136.5,188.5 142.5,188.5 144,187 144,181 ; R4.1@139.376,155.177 R2.2@139.376,157.177 140.483,157.177 142.1,158.794 142.1,172.788 ; 142.1,172.788 142.1,177.1 144,179 144,181
GPIO1: J1.44 R41.2 TP22.1 | length 32
  L1 w0.2: R41.2@107.298,145.9 107.298,147.322 107.292,147.328 107.565,147.6 v1(109.4,147.6)
  L4 w0.2: v1(111.998,132.08) 111.998,131.002 TP22.1@118,125
  L6 w0.2: v1(109.4,147.6) J1.44@110.705,147.6 111.714,147.6 111.995,147.319 111.995,141.005 112.755,140.246 112.755,137.716 112.655,137.616 112.655,136.784 112.854,136.585 112.854,135.404 111.998,134.548 v1(111.998,132.08)
GPIO1_0: C116.1 R35.2 SW4.2 U7.23 | length 91.9
  L1 w0.2: v1(171.396,180.398) U7.23@172.75,180.398 ; v1(230.304,166.8) R35.2@231.5,166.8 ; R35.2@231.367,166.919 SW4.2@234.364,166.919 ; SW4.2@234.364,167 234.6,166.764 C116.1@234.6,165
  L6 w0.2: v1(171.396,180.398) 172.519,181.521 177.832,181.521 181.517,177.836 225.668,177.836 229.082,181.25 233.25,181.25 235,179.5 235,168.25 233.55,166.8 v1(230.304,166.8)
GPIO1_1: C58.1 R32.2 SW2.2 U5.23 | length 72.2
  L1 w0.2: v1(171.396,130.398) U5.23@172.75,130.398 ; v1(230.304,116.5) R32.2@231.5,116.5 SW2.2@234.364,116.5 234.6,116.264 C58.1@234.6,114.5
  L4 w0.2: v1(171.396,130.398) 179.855,130.398 183.252,127 218.369,127 228.869,116.5 v1(230.304,116.5)
GPIO3_PWM3: J1.52
GVDD0: C77.2 TP24.1 U7.52 | length 11.4
  L1 w0.4: TP24.1@156.6,165.7 157.934,165.7 161.201,168.968 U7.52@163.25,168.968 164.454,168.968 v1@164.692,169.205
  L6 w0.6: C77.2@163.425,170.005 C77.2@163.564,170.144 ; C77.2@163.6,169.932 164.393,169.932 164.747,169.578 164.747,169.207 v1(164.748,169.205)
GVDD1: C19.2 TP8.1 U5.52 | length 4
  L1 w0.4: U5.52@163.25,118.968 164.454,118.968 v1@164.692,119.205
  L6 w0.6: C19.2@163.8,119.9 163.8,119.875 163.975,119.7 164.253,119.7 v1(164.748,119.205) 164.75,119.207 165.091,119.207 165.617,119.732 TP8.1@165.725,119.732
I2C_ADDR0: R73.1 R74.2 U7.35 | length 32.2
  L1 w0.2: R74.2@147,182.7 148,182.7 R73.1@149,182.7 149,183.47 150.53,185 165.1,185 168.987,181.113 168.987,179.959 168.528,179.499 168,179.499 ; U7.35@163.25,179.763 166.678,179.763 166.941,179.5 167.999,179.5
I2C_ADDR1: R28.1 R29.2 U5.35 | length 33.2
  L1 w0.2: R29.2@145,134 146,134 R28.1@147,134 147.049,134.049 160.549,134.049 161.4,134.9 166.64,134.9 168.5,133.04 168.5,130.001 167.999,129.5 166.941,129.5 166.678,129.763 U5.35@163.25,129.763
I2C_SCL: J1.18 J2.16 R7.1 U4.6 U5.33 U7.33 | length 187.4
  L1 w0.2: J2.16@119.05,177.47 118.181,176.601 116.101,176.601 114.5,175 114.5,162.8 113.7,162 v1(109.69,162) 109.117,162 109,161.883 109,158.015 109.515,157.5 111,157.5 113.56,154.94 121.56,154.94 v1(123.5,153) ; J2.16@119.38,177.8 124.407,177.8 125.2,177.007 125.2,168.966 126.466,167.7 133.847,167.7 134.011,167.536 134.011,166.941 R7.1@134.074,166.878 134.074,164.577 v1(133.446,163.949) U4.6@131.986,163.949 ; U5.33@163.25,131.033 165.033,131.033 v1(166,132) ; U7.33@163.25,181.033 165.033,181.033 v1(166,182)
  L6 w0.2: J2.16@119.38,177.8 120.34,176.84 128.66,176.84 129.875,175.625 147.073,175.625 149.069,177.621 151.74,177.621 155.019,180.9 164.3,180.9 165.4,182 v1(166,182) ; v1(123.5,153) 122.5,152 122.5,150.5 123.5,149.5 139,149.5 147.5,141 147.5,139.5 150,137 164.234,137 166,135.234 v1(166,132)
  L6 w0.4: v1(109.69,162) J1.18@110.705,162
I2C_SDA: J1.20 J2.18 R8.1 R19.1 U5.34 U7.34 | length 177.6
  L1 w0.2: v1(109.69,161.2) v1@109.72,161.2 ; v1(124.868,152.972) 124.84,153 124.84,154.201 123.291,155.75 113.763,155.75 110.595,158.918 110.595,160.325 v1@109.72,161.2 ; R19.1@130.75,166.6 v1(129.75,166.6) 125.981,166.6 124.316,168.265 124.316,174.5 123.556,175.26 J2.18@119.38,175.26 118.12,174 116,174 115.2,173.2 115.2,162.4 114,161.2 v1@109.72,161.2 ; U5.34@163.25,130.398 165.253,130.398 166.355,131.5 v1(167,131.5) ; U7.34@163.25,180.398 165.253,180.398 166.355,181.5 v1(167,181.5)
  L6 w0.2: J2.18@119.38,175.26 126.64,175.26 128.965,172.935 130.774,172.935 131.925,174.086 148.571,174.086 150.885,176.4 152.983,176.4 156.767,180.184 165.039,180.184 166.355,181.5 v1(167,181.5) ; v1(124.868,152.972) 125.48,152.36 140.64,152.36 141.5,151.5 141.5,149.5 149,142 161.5,142 167.5,136 167.5,132 v1(167,131.5)
  L6 w0.4: v1(109.69,161.2) J1.20@110.705,161.2
I2C_SDA_R: R19.2 U4.5 | length 1.4
  L1 w0.2: R19.2@131.914,166.636 R19.2@131.95,166.6 131.986,166.564 U4.5@131.986,165.219
MCAN_RX: J1.53
MCAN_TX: J1.51
MCASPX_ACLKR: J1.43 J2.5 | length 52.8
  L3 w0.2: v1(105.575,147.6) 104.9,147.6 104.343,148.157 104.343,182.708 112.135,190.5 J2.5@116.84,190.5
  L6 w0.4: J1.43@104.535,147.6 v1(105.575,147.6)
MCASPX_ACLKX: J1.37 J2.3 R6.2 U1.1 | length 75.1
  L1 w0.2: v1(127.883,186.664) 128.992,186.664 R6.2@129.033,186.622 ; R6.2@129.033,186.6 129.055,186.622 U1.1@131.173,186.622 U1.1@131.05,186.745
  L4 w0.2: v1(105.575,154) 106.1,154 106.4,153.7 106.4,152.37 105.93,151.9 103.6,151.9 102.25,153.25 102.25,185.25 110.04,193.04 J2.3@116.84,193.04 ; J2.3@116.84,192.71 117.17,192.71 118.11,191.77 120.646,191.77 125.753,186.664 v1(127.883,186.664)
  L6 w0.4: J1.37@104.535,154 v1(105.575,154)
MCASPX_ACLKX0: R1.2 R67.2 TP17.1 U7.27 | length 91.3
  L1 w0.2: R1.2@129.06,183.148 R67.2@130.886,183.148 130.9,183.133 v1(130.9,182.5) ; v1(170.25,183.25) 170.361,183.25 170.673,182.938 U7.27@172.75,182.938
  L4 w0.2: v1(130.9,182.5) 135.5,182.5 136.5,183.5 136.5,192.5 136.98,192.98 138.25,192.98 138.35,192.98 138.65,193.28 138.65,193.68 138.95,193.98 139.55,193.98 139.85,193.68 139.85,192.28 140.15,191.98 140.75,191.98 141.05,192.28 141.05,193.68 141.35,193.98 141.95,193.98 142.25,193.68 142.25,192.28 142.55,191.98 143.15,191.98 143.45,192.28 143.45,193.68 143.75,193.98 144.35,193.98 144.65,193.68 144.65,192.28 144.95,191.98 145.55,191.98 145.85,192.28 145.85,193.68 146.15,193.98 146.75,193.98 147.05,193.68 147.05,192.28 147.35,191.98 147.95,191.98 148.25,192.28 148.25,193.68 148.55,193.98 149.15,193.98 149.45,193.68 149.45,192.28 149.75,191.98 150.35,191.98 150.65,192.28 150.65,193.68 150.95,193.98 151.55,193.98 151.85,193.68 151.85,192.28 152.15,191.98 152.75,191.98 153.05,192.28 153.05,193.68 153.35,193.98 153.95,193.98 154.25,193.68 154.25,192.28 154.55,191.98 155.15,191.98 155.45,192.28 155.45,193.68 155.75,193.98 156.35,193.98 156.65,193.68 156.65,192.28 156.95,191.98 157.55,191.98 157.85,192.28 157.85,193.68 158.15,193.98 158.75,193.98 159.05,193.68 159.05,192.28 159.35,191.98 159.95,191.98 160.25,192.28 160.25,192.68 160.55,192.98 160.727,192.98 163.581,192.98 164.25,192.311 164.25,189.001 165.751,187.5 167,187.5 170.25,184.25 v1(170.25,183.25)
  L6 w0.2: v1(170.25,183.25) TP17.1@171,183.25 ; TP17.1@171.25,183.25 TP17.1@171,183.25 ; TP17.1@171.25,183.5 TP17.1@171,183.25
MCASPX_ACLKX0_R: R1.1 U1.3 | length 2.6
  L1 w0.2: R1.1@128.937,184.519 129.741,185.322 U1.3@131.173,185.322
MCASPX_ACLKX1: R3.2 R22.2 TP1.1 U5.27 | length 92.9
  L1 w0.2: R3.2@139.825,186.618 R22.2@139.825,187.845 v1(140.8,187.845) ; v1(171.396,132.938) U5.27@172.75,132.938
  L4 w0.2: v1(146.214,177.406) 143.395,174.587 143.395,151.605 145.5,149.5 172,149.5 175,146.5 175,137.906 171.396,134.302 v1(171.396,132.938)
  L6 w0.2: v1(140.8,187.845) 140.8,183.207 146.18,177.827 146.18,177.44 v1(146.214,177.406) ; v1(171.396,132.938) TP1.1@172.361,132.938
MCASPX_ACLKX1_R: R3.1 U1.8 | length 1.7
  L1 w0.2: U1.8@136.972,186.622 138.62,186.622 R3.1@138.625,186.618
MCASPX_AR2: J1.28 J2.19 R70.2 R78.1 | length 111.2
  L1 w0.2: R78.1@175.95,181 R70.2@175.95,182.303 v1@175.95,183.086
  L4 w0.2: J2.19@116.67,173.025 J2.19@117.145,173.025 ; J2.19@116.84,172.72 J2.19@117.145,173.025 ; J2.19@117.173,172.997 J2.19@117.145,173.025
  L6 w0.2: J1.28@110.705,158 112.1,158 114.19,160.09 114.19,169.742 116.84,172.392 J2.19@116.84,172.72 113.5,176.06 113.5,184.441 115.674,186.615 120.615,186.615 124.5,190.5 129,190.5 129.1,190.5 129.4,190.8 129.4,191.2 129.7,191.5 130.3,191.5 130.6,191.2 130.6,189.8 130.9,189.5 131.5,189.5 131.8,189.8 131.8,191.2 132.1,191.5 132.7,191.5 133,191.2 133,189.8 133.3,189.5 133.9,189.5 134.2,189.8 134.2,191.2 134.5,191.5 135.1,191.5 135.4,191.2 135.4,190.8 135.7,190.5 137,190.5 146.5,190.5 151,186 174.994,186 175.926,185.068 v1(175.926,183.158)
MCASPX_AR3: J1.30 J2.21 R25.2 R33.1 | length 113.7
  L1 w0.2: R33.1@175.85,131 R25.2@175.85,132.25 v1(175.85,133.086)
  L4 w0.2: v1(145,169.5) 146,168.5 146,151.045 146.545,150.5 173.5,150.5 176.5,147.5 176.5,133.736 v1(175.85,133.086)
  L6 w0.2: J1.30@110.705,157.2 112.5,157.2 115.2,159.9 115.2,168.54 J2.21@116.84,170.18 118.16,171.5 120.5,171.5 121.095,170.905 130.612,170.905 132.017,169.5 v1(145,169.5)
MCASPX_AX00: R14.2 R69.2 TP19.1 U7.25 | length 74.3
  L1 w0.2: v1(128.398,168.9) 128.398,169.767 R69.2@128.365,169.8 R14.2@129.7,169.8 ; v1(169.25,182.25) 169.833,181.668 U7.25@172.75,181.668
  L4 w0.2: v1@128.398,168.95 131.45,168.95 134,171.5 137.258,171.5 143.5,177.742 143.5,183.5 145.5,185.5 150,185.5 150.1,185.5 150.4,185.8 150.4,186.2 150.7,186.5 151.3,186.5 151.6,186.2 151.6,184.8 151.9,184.5 152.5,184.5 152.8,184.8 152.8,186.2 153.1,186.5 153.7,186.5 154,186.2 154,184.8 154.3,184.5 154.9,184.5 155.2,184.8 155.2,186.2 155.5,186.5 156.1,186.5 156.4,186.2 156.4,184.8 156.7,184.5 157.3,184.5 157.6,184.8 157.6,186.2 157.9,186.5 158.5,186.5 158.8,186.2 158.8,184.8 159.1,184.5 159.7,184.5 160,184.8 160,186.2 160.3,186.5 160.9,186.5 161.2,186.2 161.2,185.8 161.5,185.5 162.5,185.5 163,185 165.5,185 168.25,182.25 v1(169.25,182.25)
  L6 w0.2: v1(169.25,182.25) 170.034,182.25 170.284,182 TP19.1@170.5,182
MCASPX_AX0: J1.27 J2.15 R16.2 U3.1 | length 45.2
  L1 w0.2: v1(130.034,174) R16.2@131.15,174 U3.1@131.15,172.35
  L4 w0.2: v1(105.575,158) 106.3,158 108.225,159.925 108.225,162.615 107.75,163.09 107.75,171.03 114.52,177.8 J2.15@116.84,177.8 118.11,176.53 126.23,176.53 128.76,174 v1(130.034,174)
  L6 w0.4: J1.27@104.535,158 v1(105.575,158)
MCASPX_AX00_R: R14.1 U3.3 | length 1.5
  L1 w0.2: R14.1@129.7,171 129.75,171.05 U3.3@131.15,171.05
MCASPX_AX1: J1.29 J2.17 | length 28.4
  L4 w0.2: v1(105.575,157.2) 109.9,157.2 110.5,157.8 110.5,172.522 113.238,175.26 J2.17@116.84,175.26
  L6 w0.4: J1.29@104.535,157.2 v1(105.575,157.2)
MCASPX_AX01: R15.2 R24.2 TP3.1 U5.25 | length 74.4
  L1 w0.2: R15.2@138.4,171.1 R24.2@139.7,171.1 139.8,171 v1(140.5,171) ; v1(171.396,131.668) U5.25@172.75,131.668
  L4 w0.2: v1(140.5,171) 140.5,150.5 143.5,147.5 168,147.5 172.033,143.467 172.033,139.365 168.913,136.245 168.913,132.587 169.833,131.668 v1(171.396,131.668)
  L6 w0.2: v1(171.396,131.668) TP3.1@172.361,131.668
MCASPX_AX01_R: R15.1 U3.8 | length 1.5
  L1 w0.2: U3.8@136.95,172.35 138.35,172.35 R15.1@138.4,172.3
MCASPX_FSR: J1.41 J2.11 | length 42.1
  L3 w0.2: v1(105.575,148.4) 107.287,150.112 107.287,150.278 107.015,150.549 107.015,170.674 110.42,174.079 110.42,179.364 113.936,182.88 J2.11@116.84,182.88
  L6 w0.4: J1.41@104.535,148.4 v1(105.575,148.4)
MCASPX_FSX: J1.39 J2.9 R13.2 U2.1 | length 65.5
  L1 w0.2: v1(129.541,180.407) 130.304,181.17 R13.2@131.15,181.17 131.167,181.153 U2.1@131.167,179.54 U2.1@130.642,179.54
  L4 w0.2: v1(105.575,153.2) 104.8,153.2 104,154 104,163.5 103,164.5 103,182 106.42,185.42 J2.9@116.84,185.42 118.11,184.15 125.798,184.15 v1(129.541,180.407)
  L6 w0.4: J1.39@104.535,153.2 v1(105.575,153.2)
MCASPX_FSX0: R9.2 R68.2 TP18.1 U7.26 | length 84.9
  L1 w0.2: v1(128.4,175.911) R68.2@128.4,176.9 ; R68.2@128.4,176.989 R9.2@128.4,178.25 ; v1(169.25,183.25) 170.197,182.303 U7.26@172.75,182.303
  L4 w0.2: v1(128.4,175.911) 136.411,175.911 137.955,177.455 137.955,186.955 141,190 141.5,190 141.6,190 141.9,190.3 141.9,190.7 142.2,191 142.8,191 143.1,190.7 143.1,189.3 143.4,189 144,189 144.3,189.3 144.3,190.7 144.6,191 145.2,191 145.5,190.7 145.5,189.3 145.8,189 146.4,189 146.7,189.3 146.7,190.7 147,191 147.6,191 147.9,190.7 147.9,189.3 148.2,189 148.8,189 149.1,189.3 149.1,190.7 149.4,191 150,191 150.3,190.7 150.3,189.3 150.6,189 151.2,189 151.5,189.3 151.5,190.7 151.8,191 152.4,191 152.7,190.7 152.7,189.3 153,189 153.6,189 153.9,189.3 153.9,190.7 154.2,191 154.8,191 155.1,190.7 155.1,189.3 155.4,189 156,189 156.3,189.3 156.3,190.7 156.6,191 157.2,191 157.5,190.7 157.5,189.3 157.8,189 158.4,189 158.7,189.3 158.7,189.7 159,190 160,190 160.145,190 161.749,188.395 164.245,185.9 166.6,185.9 168.303,184.197 v1(169.25,183.25)
  L6 w0.2: TP18.1@168.25,183.25 v1(169.25,183.25)
MCASPX_FSX0_R: R9.1 U2.3 | length 1.6
  L1 w0.2: R9.1@129.6,178.25 129.61,178.24 U2.3@131.167,178.24
MCASPX_FSX1: R10.2 R23.2 TP2.1 U5.26 | length 85.7
  L1 w0.2: R10.2@139.7,179.75 R23.2@139.7,181 139.707,181.007 v1(140.54,181.007) ; v1(170.846,132.299) U5.26@172.2,132.299
  L4 w0.2: v1(144,177.191) 142,175.191 142,151 144.5,148.5 170.5,148.5 172,147 173.5,145.5 173.5,138.818 170.275,135.593 170.275,132.87 v1(170.846,132.299)
  L6 w0.2: v1(140.54,181.007) 141.493,181.007 144,178.5 v1(144,177.191) ; TP2.1@170,132.299 v1(170.846,132.299)
MCASPX_FSX1_R: R10.1 U2.8 | length 1.6
  L1 w0.2: U2.8@136.967,179.54 136.977,179.55 138.3,179.55 R10.1@138.5,179.75
MCASPX_FSX2_R: R11.1 U2.5 | length 1.7
  L1 w0.2: U2.5@136.967,177.59 138.083,177.59 138.2,177.473 138.2,177.45 138.4,177.25 R11.1@138.5,177.25
MCASPX_FSX3_R: R12.1 U2.7 | length 1.7
  L1 w0.2: U2.7@136.967,178.89 138.01,178.89 138.4,178.5 R12.1@138.5,178.5
MCASPX_SERIAL4: J1.32 J2.23 | length 17.8
  L4 w0.2: v1(109.665,156.4) 111.42,156.4 113.5,158.48 113.5,166.845 114.295,167.64 J2.23@116.84,167.64
  L6 w0.4: v1(109.665,156.4) J1.32@110.705,156.4
MCASPX_SERIAL5: J1.34 J2.25 | length 15.8
  L4 w0.2: v1(109.665,155.6) 111.65,155.6 114.295,158.245 114.295,164.545 114.85,165.1 J2.25@116.84,165.1
  L6 w0.4: v1(109.665,155.6) J1.34@110.705,155.6
MCASPX_SERIAL6: J1.38 J2.27 | length 13.7
  L4 w0.2: v1(109.665,154) 111.6,154 115,157.4 115,160.72 J2.27@116.84,162.56
  L6 w0.4: v1(109.665,154) J1.38@110.705,154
